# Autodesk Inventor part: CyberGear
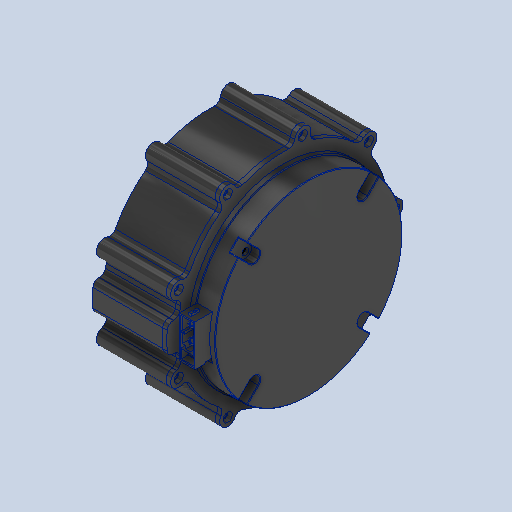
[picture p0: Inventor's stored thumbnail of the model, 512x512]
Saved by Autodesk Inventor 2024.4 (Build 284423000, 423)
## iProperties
Created: 2026-01
Part Number: CyberGear
Material: Generic
Document SubType Name: Modeling
Designer: AdminForWorker
Density: 1 g/cm^3
Appearance: Default
Title: CyberGear (1)
Author: AdminForWorker
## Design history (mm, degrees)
feature "Body1"
feature "Body2"
feature "Body3"
feature "Body4"
feature "Body5"
feature "Body6"
feature "Body7"
feature "Body8"
body "Solid1"
body "Solid2"
body "Solid3"
body "Solid4"
body "Solid5"
body "Solid6"
body "Solid7"
body "Solid8"
